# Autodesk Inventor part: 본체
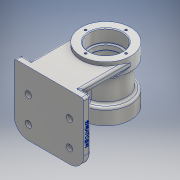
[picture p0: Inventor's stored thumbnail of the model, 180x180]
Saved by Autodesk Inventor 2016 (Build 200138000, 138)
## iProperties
Created: 2020-06
Part Number: 본체
Material: 알루미늄 6061
Document SubType Name: Modeling
Designer: pc-04
Density: 2.7 g/cm^3
Appearance: 알루미늄 - 평지
Mass: 724.444 g
Surface Area: 642.359 cm^2
Volume: 268.312 cm^3
Author: pc-04
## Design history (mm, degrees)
sketch "스케치1"
  geometry: C1 r 35 at (0, 0); 1 further point
  constraints: 1 centre point, 1 coincident
  dimensions: "d0" = 70 diameter of C1
extrude "돌출1" new body sketch "스케치1" stored distance "d1" = 22; taper "d2" = 0 deg
sketch "스케치2"
  geometry: C1 r 29 at (0, 0); 1 further point
  constraints: 1 centre point, 1 coincident
  dimensions: "d3" = 58 diameter of C1
extrude "돌출2" join sketch "스케치2" distance "d4" = 34; taper "d5" = 0 deg
sketch "스케치3"
  geometry: C1 r 35 at (0, 0); 1 further point
  constraints: 1 centre point, 1 coincident
extrude "돌출3" join sketch "스케치3" distance "d6" = 22; taper "d7" = 0 deg
fillet "모깎기1" dims "d8" = 3
sketch "스케치4"
  geometry: L1 (35, 11)-(-35, 11) reference; L2 (0, 11)-(0, -71.227); L3 (23.5, 11)-(23.5, -7); L4 (23.5, -7)-(0, -7); L5 (20, -7)-(20, -13); L6 (20, -13)-(0, -13); L7 (29, -14)-(-29, -14) reference; L8 (0, -13)-(23, -13); L9 (23, -13)-(23, -43); L10 (23, -43)-(0, -43); L11 (-35, -67)-(35, -67) reference; L12 (23.5, -67)-(23.5, -49); L13 (23.5, -49)-(0, -49); L14 (20, -49)-(20, -43); 1 further point
  constraints: 22 end point, 9 point on line, 5 perpendicular, 4 vertical, 2 parallel, 1 midpoint
  dimensions: "d9" = 47 diameter of L3 L2; "d10" = 18 distance between parallel lines of L4 L1; "d11" = 6 distance between parallel lines of L4 L6; "d12" = 30 distance between parallel lines of L10 L6; "d13" = 40 diameter of L5 L2; "d14" = 46 diameter of L9 L2; "d15" = 18 distance between parallel lines of L11 L13; "d16" = 47 diameter of L12 L2; "d17" = 40 diameter of L14 L2
revolve "회전1" sketch "스케치4" stored, may be unused: angle "d18" = 90 deg
sketch "스케치5"
  geometry: C1 r 23.5 at (0, 0); 1 further point
  constraints: 1 centre point, 1 coincident
  dimensions: "d19" = 47 diameter of C1
extrude "돌출4" cut sketch "스케치5" distance "d20" = 18; taper "d21" = 0 deg
node "작업 평면1"
node "작업 평면2"
sketch "스케치7"
  geometry: L1 (-49, -80)-(49, -80) reference; L2 (-35, 0)-(-35, -80); L3 (-35, -80)-(35, -80); L4 (35, 0)-(35, -80); A1 r 35 centre (0, 0) between (-35, 0) and (35, 0) reference; A2 r 35 centre (0, 0) between (-35, 0) and (35, 0); 1 further point
  constraints: 6 end point, 4 point on circle, 2 perpendicular, 2 point on line, 1 centre point, 1 coincident, 1 collinear, 1 tangent
extrude "돌출5" join sketch "스케치7" distance "d24" = 10; taper "d25" = 0 deg
sketch "스케치8"
  geometry: L1 (-49, -70)-(49, -70); L2 (49, -70)-(49, -80); L3 (49, -80)-(-49, -80); L4 (-49, -80)-(-49, -70); L5 (-35, -80)-(35, -80) reference; 2 further points
  constraints: 8 end point, 2 midpoint, 2 parallel, 1 horizontal, 1 perpendicular
  dimensions: "d26" = 98 distance of L2.end L3.end; "d27" = 10 distance of L1.end L2.end
extrude "돌출6" join sketch "스케치8" distance "d28" = 90; taper "d29" = 0 deg
fillet "모깎기4" dims "d32" = 3
chamfer "모따기1" distance "d34" = 1; stored, may be unused: second distance "d35" = 2, angle "d36" = 45 deg
fillet "모깎기6" dims "d41" = 3
sketch "스케치11"
  geometry: A1 r 28.5 centre (0, 0) between (0, 28.5) and (28.5, 0); 3 further points
  constraints: 4 point on circle, 1 centre point, 1 coincident
  dimensions: "d42" = 57 diameter of A1
hole "구멍1" sketch "스케치11" at (0, 28.5), (28.5, 0), (0, -28.5), (-28.5, 0) diameter "d43" = 3.242; stored, may be unused: countersink angle "d47" = 90 deg, drill point angle "d49" = 118 deg; dims "d44" = 10, "d45" = 4, "d46" = 2, "d48" = 12
sketch "스케치12"
  geometry: A1 r 28.5 centre (0, 0) between (0, 28.5) and (-28.5, 0); 3 further points
  constraints: 4 point on circle, 1 centre point, 1 coincident
  dimensions: "d50" = 57 diameter of A1
hole "구멍2" sketch "스케치12" at (0, 28.5), (-28.5, 0), (0, -28.5), (28.5, 0) diameter "d51" = 3.242; stored, may be unused: countersink angle "d55" = 90 deg, drill point angle "d57" = 118 deg; dims "d52" = 10, "d53" = 4, "d54" = 2, "d56" = 12
sketch "스케치13"
  geometry: L1 (63, -87)-(77, -87) reference; L2 (-15, 0)-(77, 0) reference; L3 (31, 0)-(31, -98.869); C1 r 4.5 at (60, -53); C2 r 4.5 at (60, -17); A1 r 15 centre (62, -15) between (77, -15) and (62, 0) reference; 1 further point
  constraints: 2 centre point, 2 end point, 1 midpoint, 1 vertical, 1 vertical alignment
  dimensions: "d59" = 9 diameter of C1; "d61" = 9 diameter of C2; "d111" = 29 distance from line of L3 C2.centre; "d112" = 36 distance of C1.centre C2.centre; "d113" = 70 distance from line of L1 C2.centre
extrude "돌출8" cut sketch "스케치13" distance "d63" = 13; taper "d64" = 0 deg
fillet "모깎기7" dims "d65" = 20
fillet "모깎기8" dims "d66" = 20
sketch "스케치14"
  geometry: L1 (3, 74)-(61, 74) reference; L2 (32, 74)-(32, -40.24); C1 r 4.5 at (3, 57); C2 r 4.5 at (3, 21); A1 r 17 centre (3, 57) between (3, 74) and (-14, 57) reference; 1 further point
  constraints: 2 centre point, 2 end point, 1 coincident, 1 midpoint, 1 vertical, 1 vertical alignment
  dimensions: "d67" = 9 diameter of C1; "d68" = 9 diameter of C2; "d69" = 36 distance of C1.centre C2.centre
extrude "돌출9" cut sketch "스케치14" distance "d70" = 13; taper "d71" = 0 deg
sketch "스케치18"
  geometry: L1 (-70, -64)-(-70, -81) reference; L2 (-70, 3)-(-70, -64) reference; L3 (-73, -84)-(-80, -84) reference; L4 (-30.121, -55)-(-30.121, -67) reference; L5 (-70, -4)-(-35, -4); L6 (-70, -4)-(-70, -72); L7 (-70, -72)-(-32.808, -58.463); L8 (-35, -8)-(35, -8) reference; L9 (-28.015, -8)-(-28.015, -48); L10 (-29, -14)-(-29, -42) reference; L11 (-28.015, -8)-(-28.015, -4); L12 (-28.015, -4)-(-35, -4); L13 (-32.808, -58.463)-(-32.808, -48); L14 (35, -48)-(-35, -48) reference; L15 (-33.166, -48)-(-28.015, -48); 2 further points
  constraints: 16 end point, 7 point on line, 2 vertical, 1 collinear, 1 parallel, 1 perpendicular
  dimensions: "d86" = 12 distance from line of L3 L6.end
extrude "돌출12" join sketch "스케치18" stored distance "d87" = 10; taper "d88" = 0 deg
fillet "모깎기10" dims "d89" = 3
fillet "모깎기11" dims "d90" = 3
node "작업 평면4"
sketch "스케치19"
  geometry: L1 (35, 22)-(-35, 22) reference; C1 r 6 at (0, -17); 1 further point
  constraints: 1 centre point
  dimensions: "d91" = 12 diameter of C1; "d92" = 39 distance from line of L1 C1.centre
extrude "돌출13" join sketch "스케치19" stored distance "d93" = 6; taper "d94" = 0 deg
sketch "스케치20"
  geometry: 2 further points
hole "구멍4" sketch "스케치20" at (0, 0) diameter "d95" = 5.188; stored, may be unused: countersink angle "d99" = 90 deg, drill point angle "d101" = 118 deg; dims "d96" = 20, "d97" = 4, "d98" = 2, "d100" = 24
fillet "모깎기12" dims "d102" = 3
sketch "스케치21"
  geometry: L1 (25.408, 6.402)-(58.592, 6.402); L2 (58.592, 6.402)-(58.592, 1.598); L3 (58.592, 1.598)-(25.408, 1.598); L4 (25.408, 1.598)-(25.408, 6.402); L5 (25.408, 4)-(58.592, 4); L6 (-3, 0)-(42, 0); L7 (0, 0)-(67, 0) reference; L8 (-3, 0)-(-3, 4); 2 further points
  constraints: 6 end point, 3 midpoint, 1 horizontal alignment, 1 point on line, 1 vertical, 1 vertical alignment, 2 other
  dimensions: "d104" = 45 distance of L6.start L6.end; "d105" = 4 distance of L6.start L8.end
feature "엠보싱1" sketch "스케치21" dims "d106" = 0.5, "d107" = 0
fillet "모깎기13" dims "d109" = 0.3
fillet "모깎기14" dims "d110" = 0.3
node "솔리드1"
other parameters: "d23" = 6, "d85" = 70 deg
